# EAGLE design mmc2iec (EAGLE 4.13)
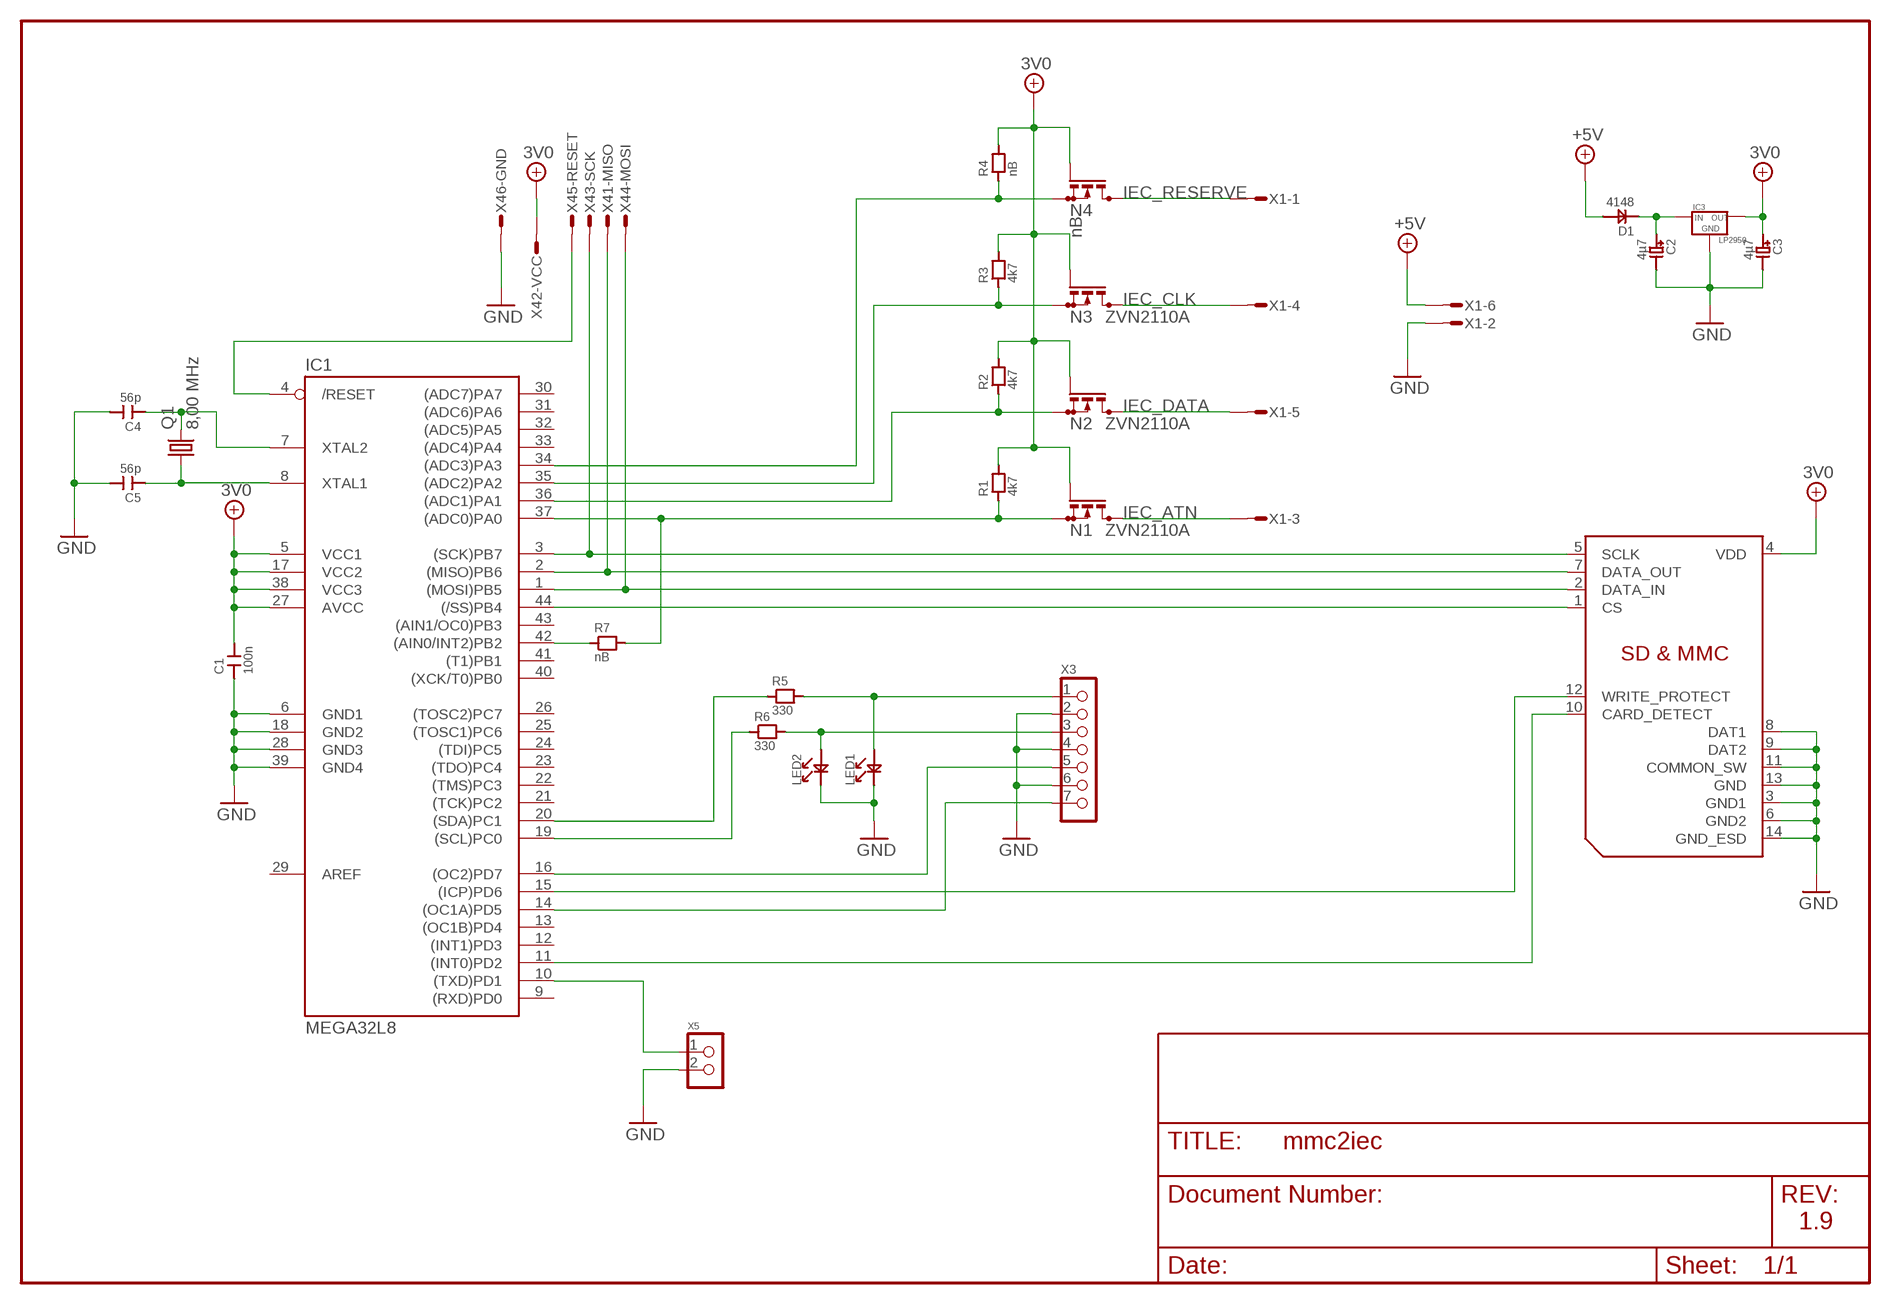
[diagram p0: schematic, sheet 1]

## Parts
C1  100n  C1206  [C1206]
C2  4µ7  C_POLTA_A  [C_TANTAL_A]
C3  4µ7  C_POLTA_A  [C_TANTAL_A]
C4  56p  C1206  [C1206]
C5  56p  C1206  [C1206]
D1  4148  DSOD-123  [SOD-123]
IC1  MEGA32L8  MEGA16/32TQFP  [TQFP44]
IC3  LP2950  LP2950_TO92S  [TO92_S]
LED1  LED1206  [LED1206]
LED2  LED1206  [LED1206]
N1  ZVN2110A  ZVN2110  [ELINE]
N2  ZVN2110A  ZVN2110  [ELINE]
N3  ZVN2110A  ZVN2110  [ELINE]
N4  nB  ZVN2110  [ELINE]
Q1  8,00 MHz  CRYTALHC49S  [HC49/S]
R1  4k7  R1206  [R1206]
R2  4k7  R1206  [R1206]
R3  4k7  R1206  [R1206]
R4  nB  R1206  [R1206]
R5  330  R1206  [R1206]
R6  330  R1206  [R1206]
R7  nB  R0603  [R0603]
X1  MICROMATCH-6_PIN  [MICROMATCH-6]
X2  SD_SCDA1A1401  [ALPS_SCDA1A1401]
X3  PINH1X7_2,54  [1X7]
X4  AVR-ISP_1X6  [1X6_ISP]
X5  PINH1X22,54  [1X2]

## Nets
3V0: C1.2 C3.1 IC1.5(VCC1) IC1.17(VCC2) IC1.27(AVCC) IC1.38(VCC3) IC3.3(OUT) N1.2(G) N2.2(G) N3.2(G) N4.2(G) R1.2 R2.2 R3.2 R4.2 X2.4(VDD) X4.2
+5V: D1.2 X1.6
/RESET: IC1.4(/RESET) X4.5
ATN: IC1.37((ADC0)PA0) N1.1(S) R1.1 R7.2
CD: IC1.11((INT0)PD2) X2.10(CARD_DETECT)
CLK: IC1.35((ADC2)PA2) N3.1(S) R3.1
DATA: IC1.36((ADC1)PA1) N2.1(S) R2.1
GND: C1.1 C2.2 C3.2 C4.2 C5.2 IC1.6(GND1) IC1.18(GND2) IC1.28(GND3) IC1.39(GND4) IC3.2(GND) LED1.1 LED2.1 X1.2 X2.3(GND1) X2.6(GND2) X2.8(DAT1) X2.9(DAT2) X2.11(COMMON_SW) X2.13(GND) X2.14(GND_ESD) X3.2 X3.4 X3.6 X4.6 X5.2
IEC_ATN: N1.3(D) X1.3
IEC_CLK: N3.3(D) X1.4
IEC_DATA: N2.3(D) X1.5
IEC_RESERVE: N4.3(D) X1.1
MISO: IC1.2((MISO)PB6) X2.7(DATA_OUT) X4.1
MOSI: IC1.1((MOSI)PB5) X2.2(DATA_IN) X4.4
N$1: IC1.14((OC1A)PD5) X3.7
N$2: C2.1 D1.1 IC3.1(IN)
N$3: IC1.10((TXD)PD1) X5.1
N$4: C5.1 IC1.8(XTAL1) Q1.1
N$5: C4.1 IC1.7(XTAL2) Q1.2
N$6: IC1.42((AIN0/INT2)PB2) R7.1
N$8: LED1.2 R5.2 X3.1
N$9: LED2.2 R6.2 X3.3
N$10: IC1.16((OC2)PD7) X3.5
PC0: IC1.19((SCL)PC0) R6.1
PC1: IC1.20((SDA)PC1) R5.1
RESERVE: IC1.34((ADC3)PA3) N4.1(S) R4.1
SCK: IC1.3((SCK)PB7) X2.5(SCLK) X4.3
SS: IC1.44((/SS)PB4) X2.1(CS)
WP: IC1.15((ICP)PD6) X2.12(WRITE_PROTECT)
Unconnected: IC1.9((RXD)PD0) IC1.12((INT1)PD3) IC1.13((OC1B)PD4) IC1.21((TCK)PC2) IC1.22((TMS)PC3) IC1.23((TDO)PC4) IC1.24((TDI)PC5) IC1.25((TOSC1)PC6) IC1.26((TOSC2)PC7) IC1.29(AREF) IC1.30((ADC7)PA7) IC1.31((ADC6)PA6) IC1.32((ADC5)PA5) IC1.33((ADC4)PA4) IC1.40((XCK/T0)PB0) IC1.41((T1)PB1) IC1.43((AIN1/OC0)PB3)

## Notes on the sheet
- 1.9

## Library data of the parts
C1 C4 C5 = 0_rr:C
C2 C3 = 0_rr:C_POL
D1 = 0_rr:D
IC1 = 0_rr:MEGA16/32: MICROCONTROLLER 16 Kbytes FLASH, 512 bytes EEPROM 1 Kbytes SRAM dual UART hardware multiplier
IC3 = 0_rr:LP2950
LED1 LED2 = 0_rr:LED
N1-N4 = 0_rr:ZVN2110
Q1 = CRYSTAL:CRYTAL: CRYSTAL
R1-R7 = 0_rr:R
X1 = 0_rr:MICROMATCH-6: MicroMaTch 6 7-215464-6 / 0-215464-6 Drawing Number C-215464 DDEController.pdf
X2 = 0_rr:SD
X3 = 0_rr:PINH1X7
X4 = 0_rr:AVR-ISP: MicroMaTch 6 7-215464-6 / 0-215464-6 Drawing Number C-215464 DDEController.pdf
X5 = 0_rr:PINH1X2

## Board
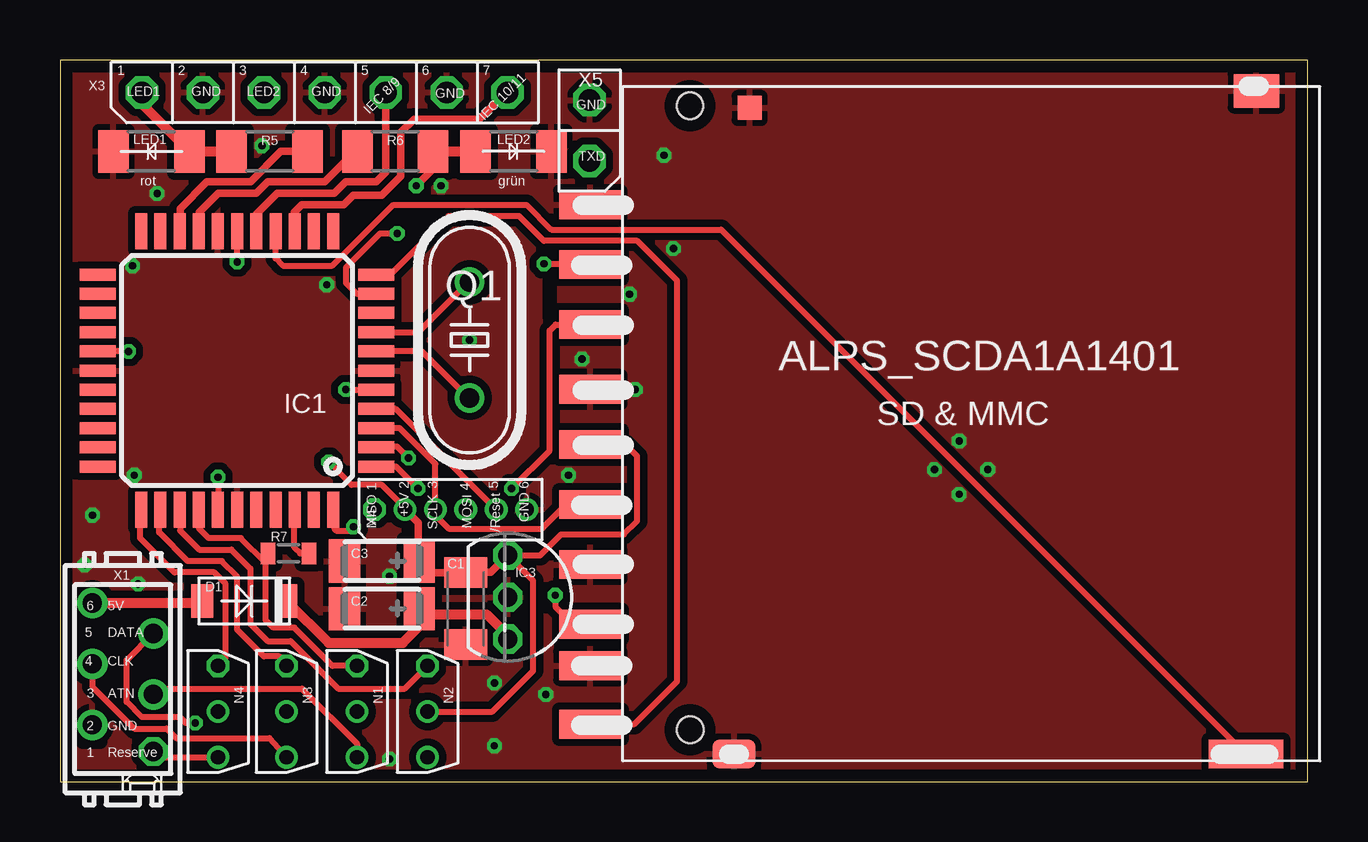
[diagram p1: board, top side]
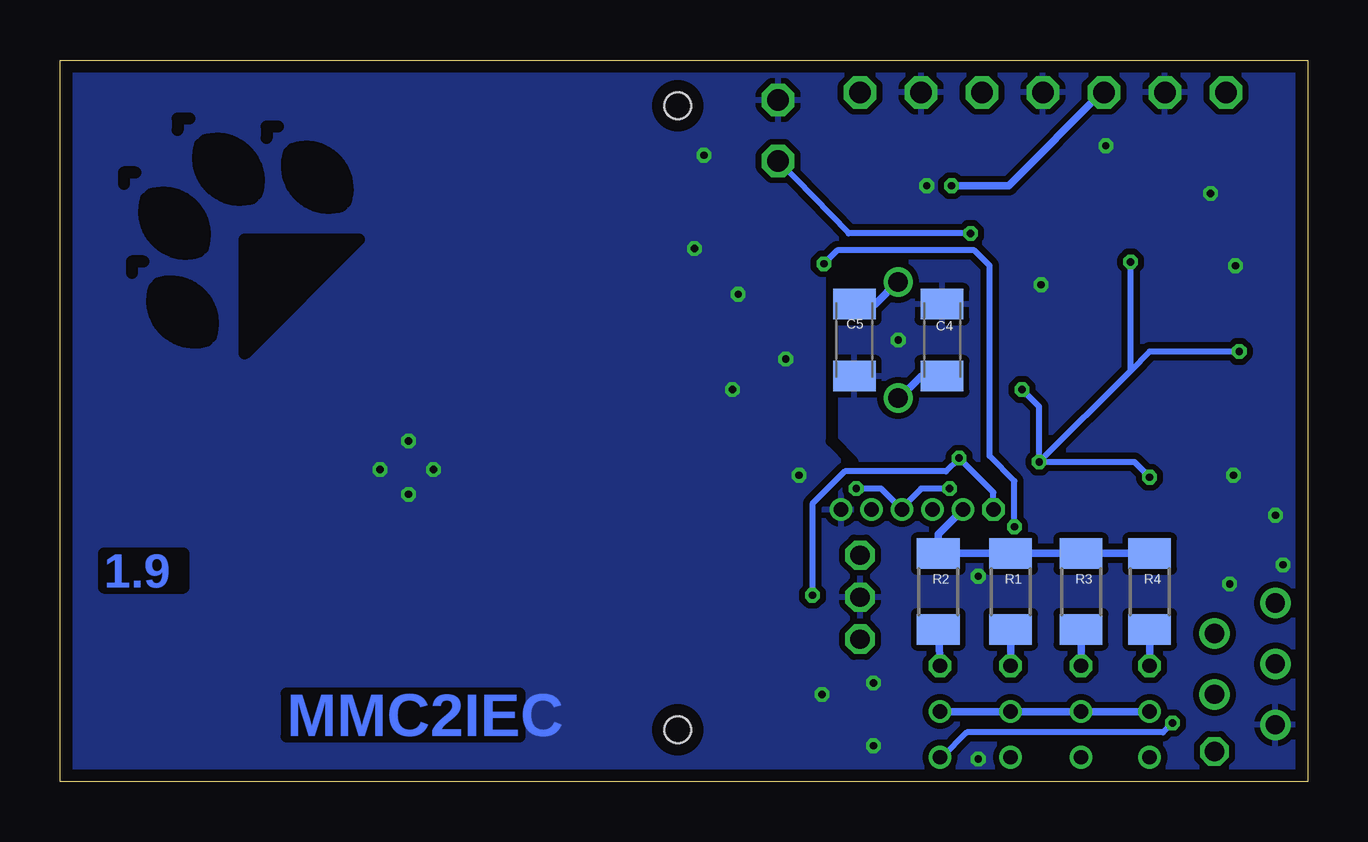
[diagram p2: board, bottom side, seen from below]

Size 51.99 x 30.08 mm. Coordinates in mm from the lower left corner, seen from the top.
Outline: 0,0 51.99,0 51.99,30.08 0,30.08 0,0
Copper layers (1*16): Top 0.035mm / dielectric 1.5mm / Bottom 0.035mm
Design rules "default": minimum track width 8mil, minimum drill 12mil, track to track 6mil, track to pad 6mil, pad to pad 6mil, via to via 6mil, smd to smd 6mil, copper to edge 20mil, drill to drill 8mil, minimum pad ring 6mil, minimum via ring 6mil, stop-mask expansion 4mil, vias tented up to drill 12mil, thermal gap 10mil
tRestrict: 2 lines
bRestrict: 2 lines

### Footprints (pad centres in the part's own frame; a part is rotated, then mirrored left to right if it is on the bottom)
C1206 = smd 1.27 x 1.778: 1 -1.5,0; 2 1.5,0
C_TANTAL_A = smd 1.3 x 1.8: 1 1.559,0; 2 -1.559,0
SOD-123 = smd 0.914 x 1.397: 1 -1.757,0; 2 1.757,0
TQFP44 = smd 1.5 x 0.5: 1 -5.8,4; 2 -5.8,3.2; 3 -5.8,2.4; 4 -5.8,1.6; 5 -5.8,0.8; 6 -5.8,0; 7 -5.8,-0.8; 8 -5.8,-1.6; 9 -5.8,-2.4; 10 -5.8,-3.2; 11 -5.8,-4; 23 5.8,-4; 24 5.8,-3.2; 25 5.8,-2.4; 26 5.8,-1.6; 27 5.8,-0.8; 28 5.8,0; 29 5.8,0.8; 30 5.8,1.6; 31 5.8,2.4; 32 5.8,3.2; 33 5.8,4 | smd 0.5 x 1.5: 12 -4,-5.8; 13 -3.2,-5.8; 14 -2.4,-5.8; 15 -1.6,-5.8; 16 -0.8,-5.8; 17 0,-5.8; 18 0.8,-5.8; 19 1.6,-5.8; 20 2.4,-5.8; 21 3.2,-5.8; 22 4,-5.8; 34 4,5.8; 35 3.2,5.8; 36 2.4,5.8; 37 1.6,5.8; 38 0.8,5.8; 39 0,5.8; 40 -0.8,5.8; 41 -1.6,5.8; 42 -2.4,5.8; 43 -3.2,5.8; 44 -4,5.8
TO92_S = drill 0.8 pad 1.219 octagon: 1 1.746,0; 2 0,0; 3 -1.746,0
LED1206 = smd 1.27 x 1.778: 1 -1.581,0; 2 1.581,0
ELINE = drill 0.6 pad 0.94 octagon: 1 -1.905,0 | drill 0.6 pad 0.94 round: 2 0,0; 3 1.905,0
HC49/S = drill 0.813 round: 1 -2.413,0; 2 2.413,0
R1206 = smd 1.27 x 1.778: 1 -1.581,0; 2 1.581,0
R0603 = smd 0.6 x 0.9: 1 -0.85,0; 2 0.85,0
MICROMATCH-6 = drill 0.8 pad 1.118 octagon: 1 3.016,1.27 | drill 0.8 pad 1.27 round: 2 1.905,-1.27; 3 0.635,1.27; 4 -0.635,-1.27; 5 -1.905,1.27; 6 -3.175,-1.27
ALPS_SCDA1A1401 = smd 2.6 x 1.2: 1 -4.176,6.875; 2 -4.176,4.375; 3 -4.176,1.675; 4 -4.176,-0.625; 5 -4.176,-3.125; 6 -4.176,-5.625; 7 -4.176,-8.109; 8 -4.176,-9.841; 9 -4.176,9.37; 10 -4.176,-12.275 | smd 1.8 x 1.2: 11 1.814,-13.516 | smd 3.1 x 1.2: 12 23.137,-13.517 | smd 1.9 x 1.4: 13 23.576,14.113 | smd 1 x 1: 14 2.463,13.399 | hole 1.1: -0.02,13.495; -0.019,-12.505
1X7 = drill 0.9 octagon: 1 -7.62,0; 2 -5.08,0; 3 -2.54,0; 4 0,0; 5 2.54,0; 6 5.08,0; 7 7.62,0
1X6_ISP = drill 0.6 pad 0.94 octagon: 1 0,0 | drill 0.6 pad 0.94 round: 2 1.27,0; 3 2.54,0; 4 3.81,0; 5 5.08,0; 6 6.35,0
1X2 = drill 0.9 pad 1.27 octagon: 1 -1.27,0; 2 1.27,0

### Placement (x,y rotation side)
C1  16.91,7.22 90 top
C2  13.41,7.22 0 top
C3  13.41,9.21 0 top
C4  15.24,18.41 90 bottom
C5  18.89,18.41 270 bottom
D1  7.68,7.54 180 top
IC1  7.38,17.15 180 top
IC3  18.65,7.7 270 top
LED1  3.81,26.27 0 top
LED2  18.89,26.27 180 top
N1  12.38,2.94 270 top
N2  15.32,2.94 270 top
N3  9.45,2.94 270 top
N4  6.59,2.94 270 top
Q1  17.07,18.42 270 top
R1  12.38,7.94 90 bottom
R2  15.4,7.94 90 bottom
R3  9.45,7.94 90 bottom
R4  6.59,7.94 90 bottom
R5  8.73,26.27 180 top
R6  13.97,26.27 0 top
R7  9.52,9.53 180 top
U$2  [LOGO_B]  44.84,23.15 315 top
X1  2.62,4.29 270 top
X2  26.27,14.68 0 top
X3  11.03,28.73 0 top
X4  13.1,11.35 0 top
X5  22.07,27.15 90 top

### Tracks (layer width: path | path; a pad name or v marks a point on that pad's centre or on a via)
3V0  (via drill 0.3)
  Top 0.254: IC1.5 v11.91,16.35 | IC1.38 6.58,11.28 6.59,11.27 v6.59,12.7 | IC1.27 v2.85,17.95 v2.86,17.94 | v7.38,21.67 IC1.17 | N2.2 15.56,2.94 18.02,2.94 19.71,4.63 19.71,8.39 IC3.3 20,9.45 20.88,10.32 23.5,10.32 24.05,10.87 24.05,13.57 23.56,14.06 X2.4 | v11.19,13.34 12.14,12.38 13.41,12.38 14.37,11.43 X4.2 | X4.2 | X4.2
  Top 0.305: 14.92,9.16 14.92,9.13 | 14.92,9.16 C3.1 14.97,9.26 15,9.29 15.57,8.72 C1.2 17.07,8.56 17.07,8.73 17.94,8.73 IC3.3 | X4.2 14.92,10.79 14.92,9.16
  Bottom 0.254: v11.19,13.34 7.22,13.34 v6.59,12.7 | v2.86,17.94 6.59,17.94 7.38,17.14 | v11.19,13.34 7.38,17.14 | 7.38,17.14 v7.38,21.67 | v11.91,16.35 11.19,15.64 v11.19,13.34
  Bottom 0.305: R3.2 6.67,9.53 R4.2 | R3.2 | R3.2 12.22,9.53 12.22,9.52 R1.2 12.23,9.53 R2.2 15.4,10.32 X4.2 | X4.2 | 9.53,2.94 | 9.53,2.94 N3.2 12.46,2.94 N1.2 15.4,2.94 N2.2 | N4.2 9.53,2.94
+5V
  Top 0.406: D1.2 6.11,7.54 6.11,7.46 X1.6
/RESET
  Top 0.254: X4.5 | X4.5 | IC1.4 13.98,15.54 X4.5
ATN
  Top 0.254: 8.57,9.13 8.57,6.75 8.89,6.43 9.76,6.43 11.35,4.84 N1.1 | 8.57,9.13 7.54,10.16 6.19,10.16 5.79,10.56 5.79,11.33 IC1.37 | 8.57,9.13 | 8.57,9.13 | R7.2 8.68,9.23 8.57,9.13
  Bottom 0.305: R1.1 N1.1
CD
  Top 0.254: X2.10 23.92,2.41 25.72,4.21 25.72,20.88 24.05,22.54 20.16,22.54 19.13,23.57 16.19,23.57 13.76,21.14 IC1.11
CLK
  Top 0.254: N3.1 9.53,4.84 9.13,5.24 8.49,5.24 7.38,6.35 7.38,7.14 7.38,8.57 6.75,9.21 5.32,9.21 4.13,10.4 4.13,11.29 IC1.35
  Bottom 0.305: N3.1 R3.1
DATA
  Top 0.254: N2.1 | N2.1 14.37,3.89 11.59,3.89 9.6,5.87 8.65,5.87 7.94,6.59 7.94,8.89 7.14,9.68 5.79,9.68 5,10.48 5,11.35 IC1.36
  Bottom 0.305: N2.1 R2.1
GND  (via drill 0.3)
  other vias: 25.16,26.11 36.43,13.02 37.47,11.99 37.47,14.21 38.66,13.02 13.73,0.95 13.73,8.57 21.19,12.78 3.1,12.78 3.02,21.51 11.11,20.72 3.25,8.25 1.35,11.11 25.56,22.23 23.73,20.32 23.97,16.35 21.75,17.62 15.88,24.84 8.41,26.51 4.05,24.53 1.03,9.05 20.24,3.65 18.1,4.13 17.07,18.41 18.1,1.51
  pour Top (isolate 0.305): 0,0 0,30.08 51.99,30.08 51.99,0
  pour Bottom (isolate 0.254): 0,0 0,30.08 51.99,30.08 51.99,0
IEC_ATN
  Top 0.254: X1.3 4.13,3.89 10.08,3.89 12.38,1.59 N1.3
IEC_CLK
  Top 0.254: N3.3 8.73,1.83 4.84,1.83 4.45,2.22 3.1,2.22 1.35,3.97 X1.4 | X1.4 | X1.4
IEC_DATA  (via drill 0.3)
  Top 0.254: X1.5 2.78,5.08 2.78,3.33 3.41,2.7 5,2.7 5.24,2.46 v5.64,2.46
  Bottom 0.254: v5.64,2.46 6.03,2.06 14.21,2.06 15.24,1.03 N2.3
IEC_RESERVE
  Top 0.254: X1.1 | X1.1 | N4.3 4.13,1.03 X1.1
MISO  (via drill 0.3)
  Top 0.254: 13.21,13.97 IC1.2 13.18,13.97 14.05,13.97 v14.53,13.49 | v20.64,7.78 20.64,7.3 21.36,6.58 X2.7
  Bottom 0.254: X4.1 13.1,12.06 v14.53,13.49 15.08,12.94 19.29,12.94 20.64,11.59 v20.64,7.78
MOSI  (via drill 0.3)
  Top 0.254: IC1.1 14,13.14 v14.92,12.22 | X2.2 20.65,19.06 20.4,18.81 20.4,13.81 v18.81,12.22
  Bottom 0.254: 16.91,11.43 | 16.91,11.43 X4.4 | v14.92,12.22 16.11,12.22 16.91,11.43 | X4.4 | X4.4 | v18.81,12.22 17.78,12.22 X4.4
N$1
  Top 0.305: X3.7 18.65,28.81 17.46,27.62 14.76,27.62 14.21,27.07 14.21,25.24 13.41,24.45 12.22,24.45 11.83,24.05 10.08,24.05 9.76,23.73 9.76,22.94 IC1.14
N$2
  Top 0.305: 15.48,6.99 15.45,7.01 C2.1
  Top 0.406: D1.1 9.45,7.54 11.19,5.79 14.29,5.79 15.48,6.99 17.78,6.99 18.81,5.95 IC3.1
N$3  (via drill 0.3)
  Top 0.254: IC1.10 12.36,20.34 11.91,20.8 11.91,21.43 13.34,22.86 v14.05,22.86
  Bottom 0.254: X5.1 | v14.05,22.86 19.13,22.86 X5.1
N$4
  Top 0.254: 17.07,20.88 | 17.07,20.88 Q1.1 | IC1.8 14.94,18.75 17.07,20.88
  Bottom 0.305: Q1.1 17.07,20.88 18.03,19.91 C5.1
N$5
  Top 0.254: 17.07,15.96 17.07,15.95 | Q1.2 17.07,15.96 | IC1.7 15.07,17.95 17.07,15.96
  Bottom 0.305: 17.07,15.96 17.07,15.95 | 17.07,15.96 Q1.2 | C4.1 16.11,16.91 17.07,15.96
N$6
  Top 0.254: R7.1 10,9.53 9.76,9.76 9.76,11.35 IC1.42
N$8
  Top 0.406: X3.1 | X3.1 3.41,28.25 LED1.2 R5.2
N$9  (via drill 0.3)
  Top 0.305: R6.2 15.55,25.55 v14.84,24.84
  Top 0.406: R6.2 LED2.2
  Bottom 0.305: X3.3 8.49,28.81 12.46,24.84 v14.84,24.84
N$10
  Top 0.305: IC1.16 8.18,23.65 9.05,24.53 11.43,24.53 11.91,25 13.18,25 13.57,25.4 X3.5 | X3.5
PC0
  Top 0.305: 5.79,22.96 IC1.19 5.78,22.87 5.79,22.86 5.79,23.73 6.59,24.53 8.18,24.53 8.65,25 11.03,25 12.3,26.27 R6.1 | R6.1
PC1
  Top 0.305: R5.1 9.21,26.27 7.94,25 6.11,25 5,23.89 5,22.78 4.98,22.8 IC1.20
RESERVE
  Top 0.254: N4.1 6.91,5.16 6.91,8.26 6.43,8.73 4.76,8.73 3.33,10.16 3.33,11.35 IC1.34
  Bottom 0.305: N4.1 | N4.1 R4.1 | N4.1
SCK
  Top 0.254: IC1.3 14.15,14.74 15.64,13.26 X4.3 | X4.3 | X4.3 | X4.3 15.64,11.11 16.19,10.56 20.08,10.56 21.03,11.51 22.07,11.51 22.1,11.54 X2.5
SS  (via drill 0.3)
  Top 0.254: X2.1 22.07,21.59 v20.16,21.59 | v12.22,10.64 12.06,10.48 11.51,10.48 11.43,10.56 11.43,11.3 IC1.44
  Bottom 0.254: v20.16,21.59 19.61,22.15 13.89,22.15 13.26,21.51 13.26,13.57 12.22,12.54 v12.22,10.64
WP
  Top 0.254: IC1.15 8.98,21.82 9.29,21.51 11.35,21.51 13.89,24.05 19.45,24.05 20.48,23.02 27.54,23.02 49.41,1.15 | 49.41,1.15 49.45,1.11 | 49.41,1.15 X2.12

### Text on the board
Bottom: 1.9 | MMC2IEC
tPlace: 1 | LED1 | 2 | GND | 3 | LED2 | 4 | GND | 5 | 6 | 7 | IEC 8/9 | GND | IEC 10/11 | GND | TXD | rot | grün | 2 | 3 | 5 | 6 | 1 | MISO | +5V | SCLK | 4 | MOSI | /Reset | GND | 6 | 5V | 5 | DATA | 4 | CLK | 3 | ATN | 2 | GND | 1 | Reserve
